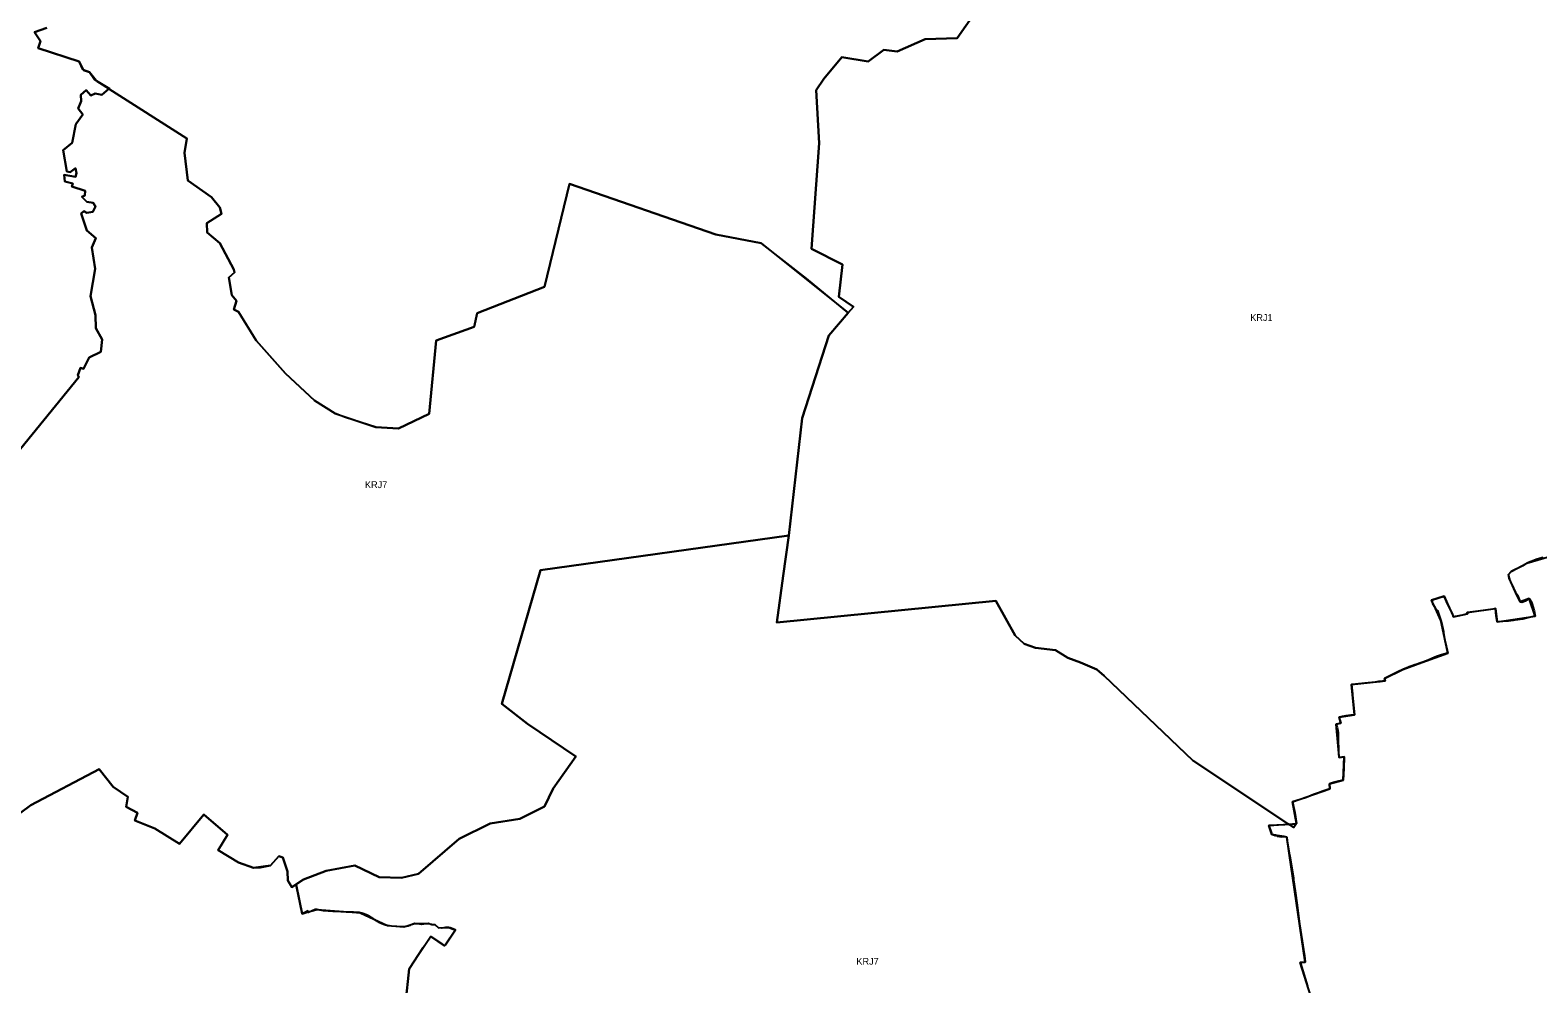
# Model space of a CAD drawing. Extents: x -563112 to -465432, y -1206259 to -1132144.
# Drawn here: x -541465 to -530418, y -1158007 to -1151020 of the extents above; entities that cross this region are included whole.
import ezdxf

# ---------------------------------------------------------------- set-up
doc = ezdxf.new("R2010")
doc.units = 0
doc.layers.add('krajiny', color=7, linetype='Continuous')

msp = doc.modelspace()

# ---------------------------------------------------------------- linework, layer by layer
at = {"layer": 'krajiny'}
for points in [[(-534419.12, -1150714.48), (-534671.39, -1151078.04), (-534906.56, -1151086.59), (-535111.79, -1151176.41), (-535210.13, -1151163.58), (-535325.58, -1151249.12), (-535516.46, -1151218.66), (-535649.58, -1151375.89), (-535706.12, -1151458.7), (-535684.74, -1151847.93), (-535740.33, -1152622.09), (-535513.71, -1152737.58), (-535539.37, -1152972.82), (-535432.47, -1153045.53), (-535471, -1153090.58), (-535776.57, -1152840.1), (-536109.19, -1152579.13), (-536439.77, -1152515.87), (-537513.3, -1152146.17), (-537696.17, -1152900.8), (-538188.27, -1153092.33), (-538212.67, -1153192.84), (-538490.18, -1153293.28), (-538540, -1153830.9), (-538765.82, -1153938.79), (-538932.38, -1153929.06), (-539155.22, -1153857.04), (-539231.12, -1153828.59), (-539381.73, -1153733.64), (-539592.66, -1153535.17), (-539808.05, -1153293.75), (-539938.78, -1153083.74), (-539973.2, -1153067.08), (-539953.41, -1153003.89), (-539987.34, -1152960.47), (-540008.03, -1152831.3), (-539966.38, -1152794.06), (-539971.87, -1152772.19), (-540074.09, -1152580.16), (-540166.84, -1152500.84), (-540171.09, -1152432.59), (-540063.55, -1152365.55), (-540075.16, -1152319.19), (-540135.98, -1152242.63), (-540309.81, -1152121.7), (-540334.37, -1151919.45), (-540316.6, -1151812.2), (-540888.2, -1151450.08), (-540974.73, -1151395.26), (-540980.02, -1151388.72), (-541029.43, -1151327.7), (-541075.65, -1151309.8), (-541079.23, -1151308.41), (-541105.79, -1151248.37), (-541405.01, -1151151.39), (-541389.7, -1151099.65), (-541432.16, -1151034.6), (-541341.55, -1151002.4)], [(-530378.68, -1154883.52), (-530422.93, -1154895.16), (-530497.97, -1154923.7), (-530529.09, -1154943.29), (-530612.88, -1154984.73), (-530631.94, -1155008.23), (-530632.46, -1155017.66), (-530628.61, -1155033.97), (-530628.22, -1155035.09), (-530625.72, -1155042.19), (-530625.25, -1155043.51), (-530622.22, -1155052.11), (-530596.92, -1155105.32), (-530595.36, -1155110.13), (-530580.87, -1155136.09), (-530567.38, -1155160.26), (-530547.02, -1155208.5), (-530535.69, -1155209.73), (-530509.07, -1155200.21), (-530482.71, -1155182.51), (-530465.57, -1155210.06), (-530458.52, -1155225.2), (-530451.75, -1155248.7), (-530444.04, -1155274.69), (-530436.49, -1155312.08), (-530443, -1155313.4), (-530470.97, -1155319.97), (-530491.22, -1155324.83), (-530527.91, -1155334.04), (-530565.75, -1155340.13), (-530587.48, -1155343.47), (-530597.97, -1155344.89), (-530632.54, -1155348.39), (-530716.69, -1155355.49), (-530722.62, -1155309.48), (-530727.59, -1155256.64), (-530747.23, -1155260.67), (-530856.41, -1155275.91), (-530913.03, -1155284.69), (-530936.21, -1155286.69), (-530933.62, -1155296.76), (-530959.38, -1155303.72), (-530981.11, -1155308.01), (-530985.16, -1155308.81), (-531035.61, -1155318.78), (-531044.49, -1155292.77), (-531054.45, -1155271.41), (-531080.12, -1155221.42), (-531082.49, -1155216.8), (-531100.43, -1155177.1), (-531101.01, -1155175.81), (-531104.24, -1155168.67), (-531104.9, -1155167.21), (-531196, -1155194.92), (-531195.78, -1155195.72), (-531193.46, -1155203.96), (-531193.21, -1155204.85), (-531191.23, -1155211.91), (-531190.2, -1155215.58), (-531189.17, -1155219.25), (-531188.97, -1155219.95), (-531177.64, -1155240.41), (-531167.9, -1155256.74), (-531159.77, -1155270.37), (-531155.91, -1155269.33), (-531153.19, -1155272.05), (-531127.79, -1155344.98), (-531118.64, -1155382.12), (-531110.16, -1155426.06), (-531108.51, -1155436.16), (-531097.35, -1155504.51), (-531095.76, -1155509.17), (-531077.44, -1155583.11), (-531079.57, -1155583.49), (-531079.9, -1155583.55), (-531125.1, -1155595.8), (-531160.05, -1155608.25), (-531234.78, -1155640.82), (-531240.08, -1155643.13), (-531268.71, -1155653.26), (-531275.9, -1155655.81), (-531309.3, -1155666.7), (-531310.16, -1155666.95), (-531314.97, -1155668.77), (-531319.65, -1155670.55), (-531346.01, -1155679.97), (-531360.88, -1155685.29), (-531364.96, -1155686.94), (-531389.05, -1155696.72), (-531406.38, -1155703.76), (-531439.19, -1155718.6), (-531448.78, -1155723.3), (-531469.31, -1155733.36), (-531541.54, -1155768.76), (-531537.25, -1155787.47), (-531557.19, -1155789.57), (-531572.49, -1155791.29), (-531576.15, -1155791.7), (-531577.14, -1155791.8), (-531578.18, -1155791.91), (-531583.16, -1155792.41), (-531584.29, -1155792.52), (-531610.53, -1155795.36), (-531685.59, -1155803.43), (-531753.82, -1155810.87), (-531782.44, -1155814.04), (-531775.92, -1155882.92), (-531775.88, -1155883.36), (-531775.82, -1155883.98), (-531775.32, -1155889.21), (-531775.3, -1155889.41), (-531761.34, -1156034.74), (-531769.53, -1156035.19), (-531825.4, -1156043.62), (-531852.89, -1156048.39), (-531873.92, -1156053.31), (-531868.11, -1156073.05), (-531867.29, -1156075.52), (-531863.01, -1156088.85), (-531860.51, -1156096.66), (-531895.63, -1156105.42), (-531887.27, -1156129.27), (-531882.59, -1156151.68), (-531881.05, -1156165.5), (-531880.64, -1156221.67), (-531879.06, -1156289.1), (-531878.43, -1156315.82), (-531873.61, -1156349.47), (-531838.2, -1156344.09), (-531840.61, -1156428.6), (-531843.25, -1156515.18), (-531877.34, -1156522.16), (-531908.85, -1156529.82), (-531911.31, -1156530.64), (-531914.37, -1156531.67), (-531943.88, -1156541.55), (-531942.4, -1156579.07), (-531993.65, -1156595.46), (-532026.14, -1156607.01), (-532060.99, -1156620.33), (-532113.67, -1156640.46), (-532120.97, -1156642.84), (-532215.09, -1156673.94), (-532198.57, -1156752.45), (-532185.34, -1156831.2), (-532205.68, -1156861.82), (-532240.95, -1156838.39), (-532244.93, -1156835.75), (-532946.65, -1156369.59), (-533595.78, -1155750.81), (-533649.23, -1155703.76), (-533768.97, -1155652.43), (-533860.91, -1155618.21), (-533952.84, -1155562.6), (-534098.24, -1155545.49), (-534181.62, -1155515.54), (-534247.9, -1155455.66), (-534389.88, -1155201.35), (-535993.46, -1155359.57), (-535948.56, -1155017.47), (-535907.08, -1154722.6), (-535808.74, -1153862.89), (-535612.05, -1153255.53), (-535471, -1153090.58), (-535432.47, -1153045.53), (-535539.37, -1152972.82), (-535513.71, -1152737.58), (-535740.33, -1152622.09), (-535684.74, -1151847.93), (-535706.12, -1151458.7), (-535649.58, -1151375.89), (-535516.46, -1151218.66), (-535325.58, -1151249.12), (-535210.13, -1151163.58), (-535111.79, -1151176.41), (-534906.56, -1151086.59), (-534671.39, -1151078.04), (-534419.12, -1150714.48)], [(-541341.55, -1151002.4), (-541432.16, -1151034.6), (-541389.7, -1151099.65), (-541405.01, -1151151.39), (-541105.79, -1151248.37), (-541075.65, -1151309.8), (-541073.92, -1151313.32), (-541029.43, -1151327.7), (-540994.22, -1151380.05), (-540980.02, -1151388.72), (-540884.56, -1151447.04), (-540888.2, -1151450.08), (-540940.61, -1151493.74), (-540988.83, -1151482.73), (-541020.47, -1151497.26), (-541054.08, -1151458.87), (-541093.75, -1151492.45), (-541090.41, -1151539.43), (-541112.37, -1151592.81), (-541077.84, -1151638.59), (-541129.79, -1151709.28), (-541157.59, -1151844.17), (-541223.84, -1151897.75), (-541196.18, -1152055.66), (-541171.35, -1152060.68), (-541131.53, -1152030.63), (-541124.06, -1152068.06), (-541133.04, -1152093.48), (-541214.45, -1152079.48), (-541210.96, -1152128.14), (-541152.22, -1152144.03), (-541159.46, -1152163.89), (-541062.51, -1152196.21), (-541063.51, -1152231.75), (-541085.64, -1152241.65), (-541050.54, -1152276.97), (-541001.93, -1152283.67), (-540986.22, -1152312.28), (-541006.66, -1152351.05), (-541048.3, -1152358.89), (-541071.74, -1152345.51), (-541091.12, -1152363.02), (-541049.71, -1152486.9), (-540983.87, -1152542.65), (-541013.96, -1152613.05), (-540987.74, -1152768.05), (-541023.31, -1152968.37), (-540984.94, -1153107.83), (-540982.51, -1153202.69), (-540938.05, -1153285.06), (-540947.22, -1153377.12), (-541032.14, -1153418.79), (-541072.79, -1153501.89), (-541095.62, -1153493.18), (-541116.1, -1153546.13), (-541107.03, -1153561.03), (-541534.8, -1154087.13)], [(-541534.8, -1154087.13), (-541107.03, -1153561.03), (-541116.1, -1153546.13), (-541095.62, -1153493.18), (-541072.79, -1153501.89), (-541032.14, -1153418.79), (-540947.22, -1153377.12), (-540938.05, -1153285.06), (-540982.51, -1153202.69), (-540984.94, -1153107.83), (-541023.31, -1152968.37), (-540987.74, -1152768.05), (-541013.96, -1152613.05), (-540983.87, -1152542.65), (-541049.71, -1152486.9), (-541091.12, -1152363.02), (-541071.74, -1152345.51), (-541048.3, -1152358.89), (-541006.66, -1152351.05), (-540986.22, -1152312.28), (-541001.93, -1152283.67), (-541050.54, -1152276.97), (-541085.64, -1152241.65), (-541063.51, -1152231.75), (-541062.51, -1152196.21), (-541159.46, -1152163.89), (-541152.22, -1152144.03), (-541210.96, -1152128.14), (-541214.45, -1152079.48), (-541133.04, -1152093.48), (-541124.06, -1152068.06), (-541131.53, -1152030.63), (-541171.35, -1152060.68), (-541196.18, -1152055.66), (-541223.84, -1151897.75), (-541157.59, -1151844.17), (-541129.79, -1151709.28), (-541077.84, -1151638.59), (-541112.37, -1151592.81), (-541090.41, -1151539.43), (-541093.75, -1151492.45), (-541054.08, -1151458.87), (-541020.47, -1151497.26), (-540988.83, -1151482.73), (-540940.61, -1151493.74), (-540888.2, -1151450.08), (-540316.6, -1151812.2), (-540334.37, -1151919.45), (-540309.81, -1152121.7), (-540135.98, -1152242.63), (-540075.16, -1152319.19), (-540063.55, -1152365.55), (-540171.09, -1152432.59), (-540166.84, -1152500.84), (-540074.09, -1152580.16), (-539971.87, -1152772.19), (-539966.38, -1152794.06), (-540008.03, -1152831.3), (-539987.34, -1152960.47), (-539953.41, -1153003.89), (-539973.2, -1153067.08), (-539938.78, -1153083.74), (-539808.05, -1153293.75), (-539592.66, -1153535.17), (-539381.73, -1153733.64), (-539231.12, -1153828.59), (-538932.38, -1153929.06), (-538765.82, -1153938.79), (-538540, -1153830.9), (-538490.18, -1153293.28), (-538212.67, -1153192.84), (-538188.27, -1153092.33), (-537696.17, -1152900.8), (-537513.3, -1152146.17), (-536439.77, -1152515.87), (-536109.19, -1152579.13), (-535471, -1153090.58), (-535612.05, -1153255.53), (-535808.74, -1153862.89), (-535907.08, -1154722.6), (-537726.41, -1154974.95), (-538008.61, -1155954.43), (-537820.48, -1156101.13), (-537465.59, -1156340.65), (-537632.34, -1156575.89), (-537696.48, -1156708.49), (-537876.06, -1156798.31), (-538094.12, -1156832.52), (-538320.74, -1156943.73), (-538620.04, -1157200.36), (-538744.03, -1157230.3), (-538906.51, -1157226.02), (-539086.09, -1157140.48), (-539295.6, -1157178.97), (-539462.36, -1157243.13), (-539547.29, -1157299.53), (-539576.66, -1157248.88), (-539578.61, -1157183.33), (-539614.35, -1157080.63), (-539642.1, -1157070.12), (-539703.72, -1157138.9), (-539828.8, -1157156.19), (-539939.26, -1157118.51), (-540086.95, -1157027.76), (-540019.37, -1156916.15), (-540192.72, -1156764.9), (-540370.92, -1156980.68), (-540551.83, -1156869.6), (-540697.78, -1156809.35), (-540678.5, -1156753.76), (-540761.56, -1156710.83), (-540749.51, -1156636.35), (-540855.58, -1156562.21), (-540959.94, -1156435.07), (-541459.18, -1156697.45), (-541871.07, -1157000.08)], [(-538715.56, -1158151.99), (-538688.72, -1157897.76), (-538686.28, -1157893.26), (-538584.13, -1157741.09), (-538536.53, -1157670.19), (-538534.86, -1157667.7), (-538533.57, -1157665.78), (-538531.75, -1157663.05), (-538531.49, -1157662.67), (-538529.8, -1157660.15), (-538459.24, -1157707.49), (-538427.77, -1157728.46), (-538424.99, -1157724.32), (-538422.2, -1157720.15), (-538417.62, -1157713.33), (-538349.35, -1157611.69), (-538353.2, -1157610.25), (-538354.11, -1157609.87), (-538354.22, -1157609.83), (-538354.43, -1157609.75), (-538357.88, -1157608.49), (-538362.59, -1157606.64), (-538362.85, -1157606.54), (-538365.12, -1157605.68), (-538368.35, -1157604.45), (-538386.54, -1157597.52), (-538397.61, -1157593.29), (-538419.97, -1157593.79), (-538421.56, -1157594.09), (-538448.21, -1157599.09), (-538473.73, -1157595.83), (-538496.54, -1157574.52), (-538522.59, -1157574.01), (-538549.62, -1157564.35), (-538595.67, -1157572.94), (-538649.69, -1157565.7), (-538677.34, -1157577.28), (-538681.46, -1157578.89), (-538691.36, -1157582.34), (-538693.85, -1157583.31), (-538700.55, -1157584.5), (-538709.92, -1157586.16), (-538726.22, -1157589.06), (-538742.89, -1157588.85), (-538777.35, -1157586.86), (-538817.51, -1157583.4), (-538832.78, -1157581.96), (-538846.94, -1157579.76), (-538861.22, -1157576.66), (-538874.91, -1157572.66), (-538889.07, -1157566.83), (-538902.61, -1157559.23), (-538939.62, -1157537.26), (-538947.31, -1157532.45), (-538986.12, -1157508.16), (-538999.41, -1157501.73), (-539034.62, -1157488.22), (-539046.12, -1157485.87), (-539054.11, -1157485.06), (-539072.43, -1157483.79), (-539095.65, -1157482.18), (-539112.55, -1157481.89), (-539149.66, -1157481.54), (-539187.75, -1157480.3), (-539247.19, -1157477.4), (-539316.45, -1157471.29), (-539343.26, -1157466.75), (-539362.07, -1157460.89), (-539375.57, -1157461.33), (-539398.57, -1157471.68), (-539425.2, -1157483.66), (-539426.37, -1157481.58), (-539427.1, -1157480.11), (-539427.52, -1157479.25), (-539428.5, -1157477.18), (-539430.74, -1157472.72), (-539443.5, -1157479.13), (-539453.25, -1157483.98), (-539463.26, -1157489.02), (-539472.06, -1157493.4), (-539514.11, -1157292.58), (-539516.78, -1157279.81), (-539534.97, -1157291.59), (-539547.29, -1157299.53), (-539517.03, -1157279.44), (-539462.36, -1157243.13), (-539295.6, -1157178.97), (-539086.09, -1157140.48), (-538906.51, -1157226.02), (-538744.03, -1157230.3), (-538620.04, -1157200.36), (-538320.74, -1156943.73), (-538094.12, -1156832.52), (-537876.06, -1156798.31), (-537696.48, -1156708.49), (-537632.34, -1156575.89), (-537465.59, -1156340.65), (-537820.48, -1156101.13), (-538008.61, -1155954.43), (-537726.41, -1154974.95), (-535907.08, -1154722.6), (-535948.56, -1155017.47), (-535993.46, -1155359.57), (-534389.88, -1155201.35), (-534247.9, -1155455.66), (-534181.62, -1155515.54), (-534098.24, -1155545.49), (-533952.84, -1155562.6), (-533860.91, -1155618.21), (-533768.97, -1155652.43), (-533649.23, -1155703.76), (-533595.78, -1155750.81), (-532946.65, -1156369.59), (-532244.93, -1156835.75), (-532240.95, -1156838.39), (-532270.8, -1156842.25), (-532389.12, -1156846.75), (-532369.89, -1156902.74), (-532368.62, -1156907.29), (-532367.25, -1156912.2), (-532360.41, -1156913.51), (-532354.04, -1156915.58), (-532341.56, -1156920.92), (-532340.21, -1156920), (-532336.51, -1156917.5), (-532335.42, -1156916.77), (-532332.31, -1156916.98), (-532329.26, -1156917.5), (-532328.03, -1156918.97), (-532327.08, -1156920.09), (-532327.19, -1156924.5), (-532294.73, -1156930.24), (-532276.32, -1156927.89), (-532275.65, -1156927.8), (-532264.41, -1156928.86), (-532259.46, -1156930.37), (-532256.19, -1156931.36), (-532254.87, -1156959.74), (-532238.98, -1157049.67), (-532235.07, -1157071.79), (-532208.58, -1157231.18), (-532207.98, -1157237.75), (-532207.8, -1157239.66), (-532207.22, -1157243.72), (-532195.64, -1157324.28), (-532180.79, -1157429.87), (-532163.38, -1157567.66), (-532156.74, -1157614.38), (-532140.33, -1157723.71), (-532128.2, -1157802.25), (-532123.16, -1157845.14), (-532122.78, -1157848.42), (-532158.46, -1157849.71), (-532157.98, -1157851.28), (-532156.79, -1157855.15), (-532105.04, -1158023.31)], [(-532035.87, -1158242.37), (-532158.46, -1157849.71), (-532122.78, -1157848.42), (-532238.98, -1157049.67), (-532256.19, -1156931.36), (-532276.32, -1156927.89), (-532328.03, -1156918.97), (-532336.51, -1156917.5), (-532367.25, -1156912.2), (-532389.12, -1156846.75), (-532244.93, -1156835.75), (-532185.34, -1156831.2), (-532215.09, -1156673.94), (-532060.99, -1156620.33), (-531942.4, -1156579.07), (-531943.88, -1156541.55), (-531843.25, -1156515.18), (-531838.2, -1156344.09), (-531873.61, -1156349.47), (-531879.06, -1156289.1), (-531895.63, -1156105.42), (-531860.51, -1156096.66), (-531873.92, -1156053.31), (-531761.34, -1156034.74), (-531782.44, -1155814.04), (-531578.18, -1155791.91), (-531572.49, -1155791.29), (-531537.25, -1155787.47), (-531541.54, -1155768.76), (-531406.38, -1155703.76), (-531268.71, -1155653.26), (-531234.78, -1155640.82), (-531077.44, -1155583.11), (-531108.51, -1155436.16), (-531127.79, -1155344.98), (-531167.9, -1155256.74), (-531196, -1155194.92), (-531104.9, -1155167.21), (-531080.12, -1155221.42), (-531035.61, -1155318.78), (-530933.62, -1155296.76), (-530936.21, -1155286.69), (-530727.59, -1155256.64), (-530716.69, -1155355.49), (-530436.49, -1155312.08), (-530482.71, -1155182.51), (-530547.02, -1155208.5), (-530580.87, -1155136.09), (-530628.61, -1155033.97), (-530631.94, -1155008.23), (-530612.88, -1154984.73), (-530497.97, -1154923.7), (-530332.64, -1154876.33)], [(-541871.07, -1157000.08), (-541459.18, -1156697.45), (-540959.94, -1156435.07), (-540855.58, -1156562.21), (-540749.51, -1156636.35), (-540761.56, -1156710.83), (-540678.5, -1156753.76), (-540697.78, -1156809.35), (-540551.83, -1156869.6), (-540370.92, -1156980.68), (-540192.72, -1156764.9), (-540019.37, -1156916.15), (-540086.95, -1157027.76), (-539939.26, -1157118.51), (-539828.8, -1157156.19), (-539776.05, -1157154.21), (-539703.72, -1157138.9), (-539642.1, -1157070.12), (-539614.35, -1157080.63), (-539578.61, -1157183.33), (-539576.66, -1157248.88), (-539547.29, -1157299.53), (-539516.78, -1157279.81), (-539472.06, -1157493.4), (-539427.1, -1157480.11), (-539398.57, -1157471.68), (-539362.07, -1157460.89), (-539072.43, -1157483.79), (-539046.12, -1157485.87), (-538947.31, -1157532.45), (-538846.94, -1157579.76), (-538726.22, -1157589.06), (-538649.69, -1157565.7), (-538549.62, -1157564.35), (-538496.54, -1157574.52), (-538473.73, -1157595.83), (-538421.56, -1157594.09), (-538397.61, -1157593.29), (-538365.12, -1157605.68), (-538362.59, -1157606.64), (-538354.43, -1157609.75), (-538354.11, -1157609.87), (-538349.35, -1157611.69), (-538424.99, -1157724.32), (-538427.77, -1157728.46), (-538529.8, -1157660.15), (-538688.72, -1157897.76), (-538715.56, -1158151.99)]]:
    msp.add_lwpolyline(points, dxfattribs=at)
msp.add_lwpolyline([(-532240.95, -1156838.39), (-532185.34, -1156831.2), (-532205.68, -1156861.82)], close=True, dxfattribs=at)

# ---------------------------------------------------------------- texts
for s, p in [('KRJ1', (-532525.02, -1153150.28)), ('KRJ7', (-539011.58, -1154374.8)), ('KRJ7', (-535410.85, -1157866.76))]:
    msp.add_text(s, height=50, dxfattribs=at).set_placement(p)

doc.saveas('drawing.dxf')
